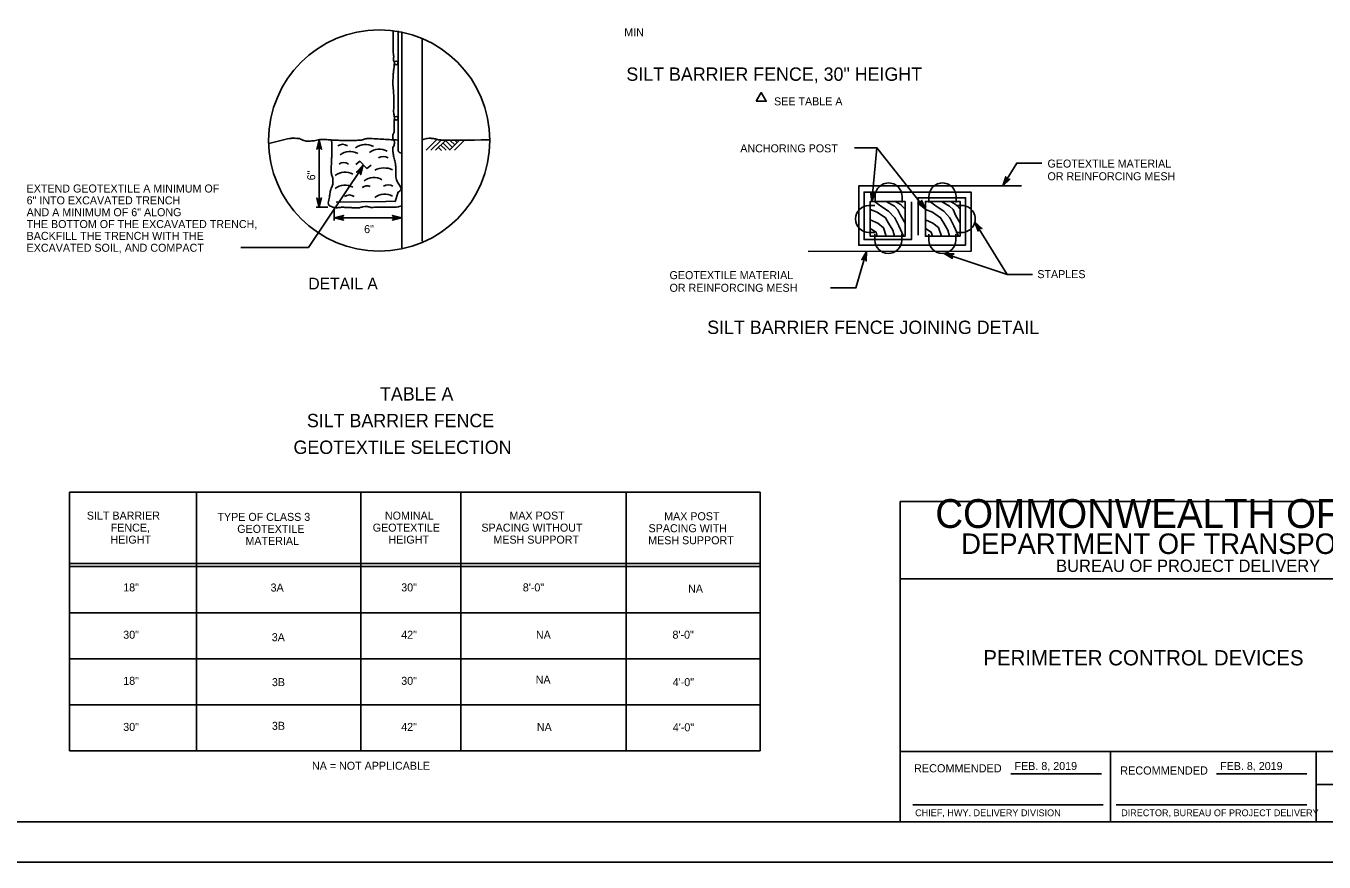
# Model space of a CAD drawing. Extents: x 636462 to 639049, y 299944 to 300538.
# Drawn here: x 636760.4 to 637246.7, y 299944.4 to 300257.6 of the extents above; entities that cross this region are included whole.
import ezdxf

# ---------------------------------------------------------------- set-up
doc = ezdxf.new("R2010")
doc.units = 0
for name, color, linetype in [('1', 7, 'Continuous'), ('Default', 7, 'Continuous'), ('PLT-BNDY', 7, 'Continuous')]:
    doc.layers.add(name, color=color, linetype=linetype)

msp = doc.modelspace()

# ---------------------------------------------------------------- linework, layer by layer
at = {"layer": '1'}
for p, q in [((637129.38, 299977.44), (637163.27, 299977.44)), ((637206.38, 299977.44), (637240.25, 299977.44)), ((637092.68, 299965.87), (637163.93, 299965.87)), ((637168.85, 299965.87), (637240.19, 299965.87))]:
    msp.add_line(p, q, dxfattribs=at)
for points in [[(637287.91, 299959.45), (637287.91, 300523.45), (636501.91, 300523.45), (636501.91, 299959.45), (637287.91, 299959.45), (637287.91, 299985.81), (637087.91, 299985.81), (637087.91, 300050.49), (637287.91, 300050.49), (637287.91, 300079.45), (637087.91, 300079.45), (637087.91, 299959.45), (637166.72, 299959.45), (637166.72, 299985.81), (637166.72, 299959.45), (637243.72, 299959.45), (637243.72, 299985.81), (637243.72, 299973.49), (637287.91, 299973.49)], [(636884.02, 300205.68), (636885.44, 300206.92), (636888.18, 300204.27), (636889.77, 300205.41)]]:
    msp.add_lwpolyline(points, dxfattribs=at)
at = {"layer": 'Default'}
for p, q in [((636899.82, 300255.73), (636899.82, 300211.19)), ((636901.2, 300255.45), (636901.2, 300174.5)), ((636908.8, 300252.99), (636908.8, 300176.96)), ((636870.24, 300214.94), (636870.24, 300189.68)), ((636910.38, 300211.04), (636914.51, 300215.17)), ((636912.12, 300211.04), (636915.84, 300214.76)), ((636913.9, 300211.04), (636917.63, 300214.76)), ((636915.85, 300212.99), (636917.8, 300211.04)), ((636916.65, 300213.79), (636919.22, 300211.22)), ((636917.55, 300214.76), (636920.17, 300212.14)), ((636919.06, 300211.04), (636922.8, 300214.78)), ((636919.34, 300214.76), (636921.05, 300213.05)), ((636920.95, 300211.04), (636924.63, 300214.72)), ((636921.15, 300214.76), (636921.96, 300213.95)), ((636901.06, 300209.95), (636901.1, 300209.95)), ((636914.96, 300212.1), (636916.07, 300210.98)), ((637079.19, 300211.98), (637077.34, 300191.88)), ((637078.51, 300193.75), (637078.51, 300191.5)), ((637088.63, 300193.75), (637088.63, 300191.5)), ((637098.69, 300193.76), (637098.7, 300191.51)), ((637108.82, 300193.76), (637108.82, 300191.51)), ((636873.48, 300189.68), (636869.19, 300189.68)), ((636875.94, 300189), (636875.94, 300184.71)), ((637076.2, 300190.37), (637078.46, 300190.37)), ((637110.95, 300190.38), (637108.7, 300190.38)), ((636875.94, 300185.76), (636901.2, 300185.76)), ((637076.21, 300180.24), (637078.46, 300180.25)), ((637078.38, 300177.42), (637078.38, 300179.67)), ((637088.5, 300177.42), (637088.5, 300179.67)), ((637098.63, 300177.43), (637098.63, 300179.68)), ((637110.95, 300180.26), (637108.7, 300180.26)), ((637108.76, 300177.43), (637108.75, 300179.68)), ((637127.99, 300164.51), (637104.43, 300172.42)), ((636776.79, 300082.98), (637035.47, 300082.98)), ((636776.79, 300082.98), (636776.79, 299986.05)), ((636824.29, 300082.98), (636824.29, 299986.05)), ((636885.93, 300082.98), (636885.93, 299986.05)), ((636923.39, 300082.98), (636923.39, 299986.05)), ((636985.25, 300082.98), (636985.25, 299986.05)), ((637035.47, 300082.98), (637035.47, 299986.05)), ((636776.79, 300056.25), (637035.47, 300056.25)), ((636776.79, 300055.12), (637035.47, 300055.12)), ((636776.79, 300037.85), (637035.47, 300037.85)), ((636776.79, 300020.58), (637035.47, 300020.58)), ((636776.79, 300003.32), (637035.47, 300003.32)), ((636776.79, 299986.05), (637035.47, 299986.05))]:
    msp.add_line(p, q, dxfattribs=at)
for points in [[(637034, 300229.4), (637037.73, 300229.4), (637035.87, 300232.63)], [(637089.72, 300178.86), (637089.72, 300191.88), (637076.69, 300191.88), (637076.7, 300178.86)], [(637110.37, 300178.87), (637110.37, 300191.89), (637097.35, 300191.89), (637097.35, 300178.87)]]:
    msp.add_lwpolyline(points, close=True, dxfattribs=at)
for points in [[(636869.63, 300211.7), (636869.41, 300211.43), (636870.24, 300214.94), (636869.63, 300211.7), (636870, 300211.9), (636870.24, 300214.94), (636870.52, 300211.91), (636870.9, 300211.73), (636870.24, 300214.94), (636871.16, 300211.45), (636870.9, 300211.73)], [(637097.35, 300189.03), (637079.19, 300211.98), (637070.81, 300211.98)], [(636886.41, 300204.62), (636866.27, 300174.64), (636840.87, 300174.64)], [(636884.62, 300202.93), (636884.29, 300202.8), (636886.74, 300205.45), (636884.62, 300202.93), (636885.04, 300202.92), (636886.74, 300205.45), (636885.5, 300202.68), (636885.74, 300202.33), (636886.74, 300205.45), (636885.83, 300201.96), (636885.74, 300202.33)], [(637126.32, 300197.73), (637131.58, 300206.27), (637141.03, 300206.27)], [(637128.58, 300200.13), (637128.92, 300200.23), (637126.32, 300197.73), (637128.58, 300200.13), (637128.16, 300200.16), (637126.32, 300197.73), (637127.72, 300200.43), (637127.5, 300200.79), (637126.32, 300197.73), (637127.43, 300201.16), (637127.5, 300200.79)], [(636899.8, 300195.38), (636898.73, 300191.87), (636896.89, 300191.94), (636895.22, 300191.8), (636876.59, 300191.62)], [(637053.48, 300173.17), (637114.45, 300173.2), (637114.44, 300195.41), (637074.39, 300195.39), (637074.4, 300177.62), (637092.2, 300177.63), (637092.19, 300191.7)], [(637133.34, 300197.74), (637072.38, 300197.71), (637072.39, 300175.49), (637112.43, 300175.51), (637112.43, 300193.28), (637094.63, 300193.28), (637094.63, 300179.21)], [(637078.27, 300195.04), (637078.52, 300195.29), (637077.34, 300191.88), (637078.27, 300195.04), (637077.88, 300194.88), (637077.34, 300191.88), (637077.36, 300194.92), (637077.01, 300195.14), (637077.34, 300191.88), (637076.78, 300195.44), (637077.01, 300195.14)], [(636870.88, 300192.91), (636871.1, 300193.18), (636870.24, 300189.68), (636870.88, 300192.91), (636870.5, 300192.71), (636870.24, 300189.68), (636869.98, 300192.71), (636869.6, 300192.89), (636870.24, 300189.68), (636869.35, 300193.17), (636869.6, 300192.89)], [(637076.69, 300188.91), (637079.32, 300187.82), (637082.37, 300185.75), (637083.57, 300183.79), (637085.1, 300181.07), (637085.76, 300178.86)], [(637078.34, 300191.88), (637081.06, 300189.89), (637083.57, 300188.26), (637085.86, 300185.75), (637087.39, 300182.7), (637089.14, 300178.86)], [(637082.7, 300191.88), (637085.75, 300190.11), (637087.06, 300188.8), (637088.15, 300186.51), (637089.72, 300183.79)], [(637095.84, 300191.96), (637095.85, 300192.31), (637097.35, 300189.03), (637095.84, 300191.96), (637095.67, 300191.57), (637097.35, 300189.03), (637095.27, 300191.24), (637094.86, 300191.15), (637097.35, 300189.03), (637094.48, 300191.21), (637094.86, 300191.15)], [(637097.35, 300188.91), (637099.98, 300187.83), (637103.03, 300185.76), (637104.23, 300183.8), (637105.76, 300181.08), (637106.41, 300178.87)], [(637098.99, 300191.89), (637101.72, 300189.9), (637104.23, 300188.26), (637106.52, 300185.76), (637108.05, 300182.71), (637109.8, 300178.87)], [(637103.35, 300191.89), (637106.41, 300190.12), (637107.72, 300188.81), (637108.81, 300186.52), (637110.37, 300183.8)], [(636879.17, 300185.15), (636879.44, 300184.92), (636875.94, 300185.76), (636879.17, 300185.15), (636878.97, 300185.52), (636875.94, 300185.76), (636878.97, 300186.04), (636879.15, 300186.42), (636875.94, 300185.76), (636879.43, 300186.67), (636879.15, 300186.42)], [(636897.97, 300186.42), (636897.7, 300186.64), (636901.2, 300185.76), (636897.97, 300186.42), (636898.17, 300186.04), (636901.2, 300185.76), (636898.17, 300185.52), (636897.99, 300185.14), (636901.2, 300185.76), (636897.7, 300184.89), (636897.99, 300185.14)], [(637076.7, 300184.98), (637079.54, 300183.79), (637081.61, 300182.05), (637082.7, 300178.86)], [(637097.35, 300184.99), (637100.2, 300183.8), (637102.27, 300182.06), (637103.36, 300178.87)], [(637115.88, 300184.17), (637127.99, 300164.51), (637137.44, 300164.51)], [(637117.11, 300181.11), (637117.07, 300180.76), (637115.88, 300184.17), (637117.11, 300181.11), (637117.31, 300181.48), (637115.88, 300184.17), (637117.75, 300181.77), (637118.16, 300181.82), (637115.88, 300184.17), (637118.53, 300181.72), (637118.16, 300181.82)], [(637076.7, 300181.72), (637078.89, 300180.41), (637079.32, 300178.86)], [(637097.35, 300181.73), (637099.54, 300180.42), (637099.98, 300178.87)], [(637075.34, 300173.18), (637071.31, 300159.48), (637061.86, 300159.48)], [(637073.82, 300170.25), (637073.54, 300170.06), (637075.34, 300173.18), (637073.82, 300170.25), (637074.24, 300170.34), (637075.34, 300173.18), (637074.74, 300170.2), (637075.05, 300169.92), (637075.34, 300173.18), (637075.22, 300169.58), (637075.05, 300169.92)], [(637107.31, 300170.83), (637107.5, 300170.54), (637104.43, 300172.42), (637107.31, 300170.83), (637107.24, 300171.25), (637104.43, 300172.42), (637107.39, 300171.75), (637107.68, 300172.05), (637104.43, 300172.42), (637108.03, 300172.21), (637107.68, 300172.05)]]:
    msp.add_lwpolyline(points, dxfattribs=at)
for centre in [(636899.13, 300243.75), (636899.13, 300223.03)]:
    msp.add_circle(centre, 0.691, dxfattribs=at)
for centre, radius, start, end in [((636892.78, 300214.73), 41.44, 180, 90), ((636892.78, 300214.73), 41.44, 90, 180), ((636879.02, 300210.2), 3.08, 54.1888, 125.8112), ((636887.6, 300207.23), 6.01, 60.5229, 127.6484), ((636881.75, 300204.62), 6.01, 60.5229, 127.6484), ((636892.76, 300205.45), 6.01, 60.5229, 127.6484), ((636894.25, 300205.68), 3.08, 54.1888, 125.8112), ((636901.06, 300211.19), 1.24, 180, 270), ((636879.5, 300203.38), 3.08, 54.1888, 125.8112), ((636894.59, 300196.78), 7.65, 65.9176, 117.3555), ((636879.95, 300196.85), 6.01, 60.5229, 127.6484), ((636890.8, 300194.8), 6.01, 60.5229, 127.6484), ((637083.57, 300193.75), 5.06, 0.0259, 180.0259), ((637103.76, 300193.76), 5.06, 0.0259, 180.0259), ((636879.9, 300191.96), 6.01, 60.5229, 127.6484), ((636881.57, 300191.22), 3.08, 54.1888, 125.8112), ((636888.22, 300194.65), 3.1, 67.5862, 126.6638), ((636894.78, 300188.6), 6.01, 60.5229, 127.6484), ((636896.12, 300195.07), 3.08, 54.1888, 125.8112), ((637076.21, 300185.31), 5.06, 90.0259, 270.0259), ((637110.95, 300185.32), 5.06, 270.0259, 90.0259), ((637083.44, 300177.42), 5.06, 180.0259, 0.0259), ((637103.69, 300177.43), 5.06, 180.0259, 0.0259)]:
    msp.add_arc(centre, radius, start, end, dxfattribs=at)
for points, degree in [([(636897.97, 300255.85), (636897.95, 300248.58), (636897.95, 300248.22), (636897.98, 300247.86), (636898, 300247.44), (636898.13, 300247.04), (636898.17, 300246.62), (636898.21, 300246.09), (636898.04, 300245.55), (636898.07, 300245.01), (636898.1, 300244.58), (636898.45, 300244.18), (636898.44, 300243.75), (636898.38, 300242.12), (636898.05, 300240.49), (636897.98, 300238.85), (636897.93, 300237.91), (636897.85, 300236.96), (636897.88, 300236.01), (636897.92, 300234.78), (636898.11, 300233.55), (636898.17, 300232.31), (636898.21, 300231.37), (636898.24, 300230.42), (636898.26, 300229.47), (636898.29, 300228.08), (636898.15, 300226.69), (636898.17, 300225.3), (636898.18, 300224.54), (636898.44, 300223.79), (636898.44, 300223.03), (636898.43, 300222.43), (636898.37, 300221.83), (636898.36, 300221.23), (636898.33, 300220.22), (636898.38, 300219.2), (636898.36, 300218.19), (636898.34, 300217.6), (636897.94, 300217.06), (636897.88, 300216.49), (636897.78, 300215.51), (636898.51, 300214.52), (636898.45, 300213.55), (636898.41, 300212.82), (636897.78, 300212.13), (636897.82, 300211.4), (636897.88, 300210.58), (636897.99, 300209.74), (636898.15, 300208.92), (636898.34, 300207.98), (636898.69, 300207.07), (636898.81, 300206.12), (636899.01, 300204.64), (636898.9, 300203.14), (636898.98, 300201.66), (636899.09, 300199.55), (636901.73, 300196.4), (636899.8, 300195.38), (636899.74, 300195.34), (636899.66, 300195.43), (636899.59, 300195.45)], 3), ([(636851.35, 300213.64), (636859.11, 300215.48), (636860.13, 300215.63), (636861.56, 300215.47), (636862.79, 300215.61), (636864.54, 300214.48), (636866.33, 300214.5), (636868.33, 300214.52), (636870.36, 300215.14), (636872.39, 300215.07), (636874, 300215.01), (636875.61, 300214.83), (636877.22, 300214.78), (636879.81, 300214.71), (636882.41, 300214.7), (636884.99, 300214.78), (636886.46, 300214.83), (636887.88, 300215.52), (636889.35, 300215.45), (636892.26, 300215.3), (636895.16, 300215.12), (636898.07, 300214.97), (636898.67, 300214.94), (636899.27, 300214.91), (636899.87, 300214.88)], 3), ([(636901.2, 300190.24), (636900.42, 300190), (636899.64, 300189.78), (636898.83, 300189.76), (636897.91, 300189.75), (636897, 300189.77), (636896.08, 300189.76), (636894.03, 300189.75), (636891.97, 300189.68), (636889.92, 300189.67), (636889.28, 300189.67), (636888.66, 300189.94), (636888.03, 300189.95), (636886.67, 300189.98), (636885.32, 300189.42), (636883.95, 300189.48), (636882.59, 300189.54), (636881.23, 300189.6), (636879.88, 300189.67), (636878.23, 300189.75), (636876.57, 300189.37), (636874.93, 300189.94), (636873.3, 300190.5), (636874.09, 300193.2), (636874.28, 300194.79), (636874.48, 300196.4), (636875.46, 300198), (636875.42, 300199.62), (636875.39, 300200.97), (636874.73, 300202.32), (636874.76, 300203.7), (636874.79, 300205.27), (636874.94, 300206.85), (636874.95, 300208.43), (636874.96, 300210.58), (636874.98, 300212.73), (636874.93, 300214.87)], 3), ([(636908.97, 300214.97), (636909.98, 300215.34), (636910.99, 300215.59), (636912, 300215.54), (636913.49, 300215.47), (636914.96, 300214.94), (636916.46, 300214.88), (636917.88, 300214.82), (636919.3, 300214.76), (636920.72, 300214.78), (636922.65, 300214.81), (636924.58, 300214.85), (636934.22, 300214.95)], 3), ([(637086.08, 300191.88), (637088.15, 300190.65), (637088.15, 300190.65), (637089.72, 300189.02)], 2), ([(637106.74, 300191.89), (637108.81, 300190.66), (637108.81, 300190.66), (637110.37, 300189.03)], 2)]:
    msp.add_open_spline(points, degree=degree, dxfattribs=at)
at = {"layer": 'PLT-BNDY'}
msp.add_lwpolyline([(636461.91, 300538.45), (637302.91, 300538.45), (637302.91, 299944.45), (636461.91, 299944.45)], close=True, dxfattribs=at)

# ---------------------------------------------------------------- texts
at = {"layer": '1'}
for s, height, p in [('COMMONWEALTH OF PENNSYLVANIA', 10.7834, (637101.07, 300069.59)), ('DEPARTMENT OF TRANSPORTATION', 7.6843, (637110.75, 300059.84)), ('BUREAU OF PROJECT DELIVERY', 4.6221, (637146.32, 300053.11)), ('RECOMMENDED', 3.048, (637093.08, 299978.04)), ('FEB. 8, 2019', 3, (637130.75, 299978.92)), ('RECOMMENDED', 3.048, (637170.32, 299977.21)), ('FEB. 8, 2019', 3, (637207.74, 299978.92)), ('APPROVED', 0.0192, (637130.94, 299977.38)), ('APPROVED', 0.0192, (637130.94, 299977.38)), ('APPROVED', 0.0192, (637130.94, 299977.38)), ('APPROVED', 0.0192, (637130.94, 299977.38)), ('CHIEF, HWY. DELIVERY DIVISION', 2.54, (637093.5, 299961.62)), ('DIRECTOR, BUREAU OF PROJECT DELIVERY', 2.54, (637170.69, 299961.62))]:
    msp.add_text(s, height=height, dxfattribs=at).set_placement(p)
at = {"layer": 'Default'}
for s, height, p in [('MIN', 2.998, (636984.56, 300253.76)), ('SILT BARRIER FENCE, 30" HEIGHT', 4.9967, (636985.34, 300237.07)), ('SEE TABLE A', 2.998, (637040.67, 300227.88)), ('ANCHORING POST', 2.998, (637028.01, 300210.27)), ('GEOTEXTILE MATERIAL ', 2.998, (637143.09, 300204.56)), ('EXTEND GEOTEXTILE A MINIMUM OF', 2.998, (636760.68, 300195.23)), ('OR REINFORCING MESH', 2.998, (637143.09, 300199.82)), ('6" INTO EXCAVATED TRENCH', 2.998, (636760.68, 300190.79)), ('AND A MINIMUM OF 6" ALONG', 2.998, (636760.68, 300186.35)), ('THE BOTTOM OF THE EXCAVATED TRENCH,', 2.998, (636760.68, 300181.91)), ('BACKFILL THE TRENCH WITH THE', 2.998, (636760.68, 300177.48)), ('6"', 2.998, (636887.11, 300180.02)), ('EXCAVATED SOIL, AND COMPACT', 2.998, (636760.68, 300173.04)), ('GEOTEXTILE MATERIAL ', 2.998, (637001.51, 300162.78)), ('STAPLES', 2.998, (637139.28, 300163.15)), ('DETAIL A', 4.372, (636866.23, 300158.93)), ('OR REINFORCING MESH', 2.998, (637001.51, 300158.04)), ('SILT BARRIER FENCE JOINING DETAIL', 4.9967, (637015.61, 300142.24)), ('TABLE A', 4.997, (636893.05, 300117.31)), ('SILT BARRIER FENCE', 4.9967, (636865.67, 300107.32)), ('GEOTEXTILE SELECTION', 4.9967, (636860.65, 300097.32)), ('SILT BARRIER', 2.998, (636783.24, 300072.71)), ('TYPE OF CLASS 3', 2.998, (636832.16, 300072.23)), ('NOMINAL', 2.998, (636894.9, 300072.71)), ('MAX POST', 2.998, (636941.54, 300072.71)), ('MAX POST', 2.998, (636999.5, 300072.47)), ('FENCE,', 2.998, (636792.18, 300068.21)), ('GEOTEXTILE', 2.998, (636839.58, 300067.74)), ('GEOTEXTILE', 2.998, (636890.33, 300068.21)), ('SPACING WITHOUT', 2.998, (636931.04, 300068.21)), ('SPACING WITH', 2.998, (636993.64, 300067.98)), ('HEIGHT', 2.998, (636792.12, 300063.72)), ('MATERIAL', 2.998, (636842.65, 300063.24)), ('HEIGHT', 2.998, (636896.25, 300063.72)), ('MESH SUPPORT', 2.998, (636935.54, 300063.72)), ('MESH SUPPORT', 2.998, (636993.5, 300063.48)), ('18"', 2.998, (636796.87, 300045.81)), ('3A', 2.998, (636852.07, 300045.77)), ('30"', 2.998, (636901.01, 300045.81)), ('8\'-0"', 2.998, (636946.55, 300045.81)), ('NA', 2.998, (637008.47, 300045.33)), ('30"', 2.998, (636796.87, 300028.09)), ('3A', 2.998, (636852.51, 300027.16)), ('42"', 2.998, (636901.01, 300028.09)), ('NA', 2.998, (636951.48, 300028.06)), ('8\'-0"', 2.998, (637002.62, 300028.1)), ('PERIMETER CONTROL DEVICES', 5.7257, (637119.04, 300018.1)), ('18"', 2.998, (636796.87, 300010.82)), ('30"', 2.998, (636901.01, 300010.82)), ('NA', 2.998, (636951.38, 300011.27)), ('3B', 2.998, (636852.56, 300010.34)), ('4\'-0"', 2.998, (637002.7, 300010.34)), ('30"', 2.998, (636796.87, 299993.56)), ('3B', 2.998, (636852.56, 299993.97)), ('42"', 2.998, (636901.01, 299993.56)), ('NA', 2.998, (636951.81, 299993.52)), ('4\'-0"', 2.998, (637002.73, 299993.41)), ('NA = NOT APPLICABLE', 2.998, (636867.58, 299979.02))]:
    msp.add_text(s, height=height, dxfattribs=at).set_placement(p)
msp.add_text('6"', height=2.998, rotation=90, dxfattribs=at).set_placement((636868.78, 300199.78))

doc.saveas('drawing.dxf')
